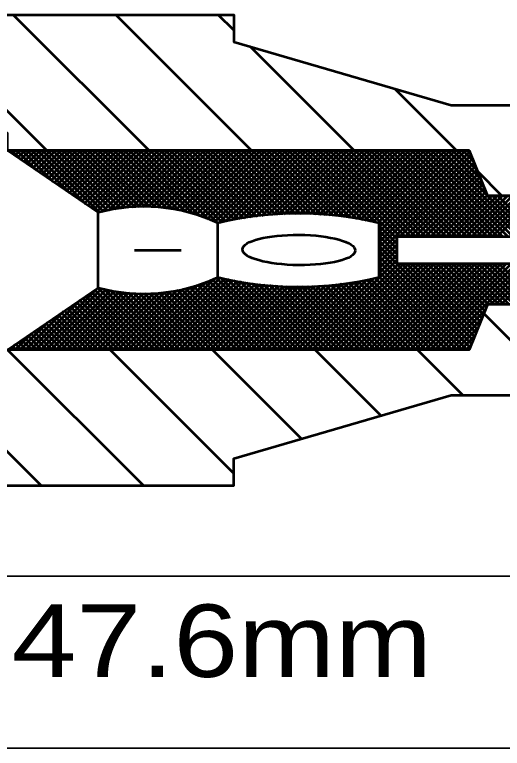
# Model space of a CAD drawing. Extents: x -32 to 824, y -6 to 538.
# Drawn here: x 645.6 to 661.75, y 243.33 to 267.63 of the extents above; entities that cross this region are included whole.
import ezdxf

# ---------------------------------------------------------------- set-up
doc = ezdxf.new("R2010")
doc.units = 0
doc.header["$LTSCALE"] = 1.1
doc.layers.add('1', color=7, linetype='Continuous', lineweight=53)

msp = doc.modelspace()

# ---------------------------------------------------------------- linework, layer by layer
at = {"layer": '1'}
for p, q in [((646.662, 263.133), (642.162, 267.633)), ((650.056, 263.133), (645.556, 267.633)), ((653.45, 263.133), (648.95, 267.633)), ((652.858, 267.12), (652.344, 267.633)), ((656.844, 263.133), (653.404, 266.574)), ((660.239, 263.133), (658.195, 265.176)), ((648.369, 261.079), (645.369, 263.133)), ((645.803, 262.836), (645.506, 263.133)), ((645.606, 262.971), (645.768, 263.133)), ((646.341, 262.468), (645.676, 263.133)), ((645.707, 262.902), (645.938, 263.133)), ((645.808, 262.833), (646.108, 263.133)), ((646.879, 262.099), (645.846, 263.133)), ((645.908, 262.764), (646.277, 263.133)), ((646.009, 262.695), (646.447, 263.133)), ((647.418, 261.731), (646.015, 263.133)), ((646.11, 262.626), (646.617, 263.133)), ((647.956, 261.362), (646.185, 263.133)), ((646.211, 262.557), (646.787, 263.133)), ((646.311, 262.488), (646.956, 263.133)), ((648.401, 261.087), (646.355, 263.133)), ((646.412, 262.419), (647.126, 263.133)), ((646.513, 262.35), (647.296, 263.133)), ((648.539, 261.119), (646.524, 263.133)), ((646.614, 262.281), (647.465, 263.133)), ((648.677, 261.15), (646.694, 263.133)), ((646.714, 262.212), (647.635, 263.133)), ((646.815, 262.143), (647.805, 263.133)), ((648.817, 261.18), (646.864, 263.133)), ((646.916, 262.074), (647.975, 263.133)), ((647.016, 262.005), (648.144, 263.133)), ((648.966, 261.201), (647.033, 263.133)), ((647.117, 261.936), (648.314, 263.133)), ((649.115, 261.221), (647.203, 263.133)), ((647.218, 261.867), (648.484, 263.133)), ((647.319, 261.798), (648.653, 263.133)), ((649.264, 261.242), (647.373, 263.133)), ((647.419, 261.73), (648.823, 263.133)), ((647.52, 261.661), (648.993, 263.133)), ((649.416, 261.26), (647.543, 263.133)), ((647.621, 261.591), (649.162, 263.133)), ((649.581, 261.265), (647.712, 263.133)), ((647.722, 261.523), (649.332, 263.133)), ((647.822, 261.454), (649.502, 263.133)), ((649.745, 261.27), (647.882, 263.133)), ((647.923, 261.385), (649.672, 263.133)), ((648.024, 261.316), (649.841, 263.133)), ((649.909, 261.275), (648.052, 263.133)), ((648.125, 261.247), (650.011, 263.133)), ((650.084, 261.271), (648.221, 263.133)), ((648.225, 261.178), (650.181, 263.133)), ((648.326, 261.109), (650.35, 263.133)), ((650.267, 261.257), (648.391, 263.133)), ((648.495, 261.108), (650.52, 263.133)), ((650.45, 261.244), (648.561, 263.133)), ((648.716, 261.159), (650.69, 263.133)), ((650.639, 261.225), (648.731, 263.133)), ((650.845, 261.188), (648.9, 263.133)), ((648.921, 261.195), (650.86, 263.133)), ((651.052, 261.151), (649.07, 263.133)), ((649.118, 261.221), (651.029, 263.133)), ((651.271, 261.101), (649.24, 263.133)), ((649.314, 261.249), (651.199, 263.133)), ((651.51, 261.032), (649.409, 263.133)), ((649.498, 261.262), (651.369, 263.133)), ((651.749, 260.963), (649.579, 263.133)), ((649.673, 261.268), (651.538, 263.133)), ((652.034, 260.848), (649.749, 263.133)), ((649.848, 261.273), (651.708, 263.133)), ((652.318, 260.734), (649.918, 263.133)), ((650.02, 261.276), (651.878, 263.133)), ((652.458, 260.763), (650.088, 263.133)), ((650.178, 261.264), (652.047, 263.133)), ((652.598, 260.793), (650.258, 263.133)), ((650.336, 261.252), (652.217, 263.133)), ((652.738, 260.823), (650.428, 263.133)), ((650.495, 261.241), (652.387, 263.133)), ((652.878, 260.853), (650.597, 263.133)), ((650.647, 261.224), (652.557, 263.133)), ((653.025, 260.875), (650.767, 263.133)), ((650.791, 261.198), (652.726, 263.133)), ((650.935, 261.172), (652.896, 263.133)), ((653.175, 260.894), (650.937, 263.133)), ((651.079, 261.146), (653.066, 263.133)), ((653.326, 260.914), (651.106, 263.133)), ((651.219, 261.117), (653.235, 263.133)), ((653.476, 260.934), (651.276, 263.133)), ((651.35, 261.079), (653.405, 263.133)), ((653.625, 260.953), (651.446, 263.133)), ((651.482, 261.04), (653.575, 263.133)), ((651.614, 261.002), (653.745, 263.133)), ((653.776, 260.973), (651.615, 263.133)), ((651.745, 260.964), (653.914, 263.133)), ((653.926, 260.993), (651.785, 263.133)), ((651.867, 260.916), (654.084, 263.133)), ((654.076, 261.012), (651.955, 263.133)), ((651.987, 260.867), (654.254, 263.133)), ((652.108, 260.818), (654.423, 263.133)), ((654.239, 261.019), (652.125, 263.133)), ((652.228, 260.769), (654.593, 263.133)), ((654.404, 261.023), (652.294, 263.133)), ((652.375, 260.746), (654.763, 263.133)), ((654.57, 261.028), (652.464, 263.133)), ((652.591, 260.792), (654.932, 263.133)), ((654.735, 261.032), (652.634, 263.133)), ((654.9, 261.036), (652.803, 263.133)), ((652.807, 260.838), (655.102, 263.133)), ((655.066, 261.04), (652.973, 263.133)), ((653.012, 260.873), (655.272, 263.133)), ((655.231, 261.045), (653.143, 263.133)), ((653.207, 260.898), (655.442, 263.133)), ((655.408, 261.038), (653.312, 263.133)), ((653.402, 260.924), (655.611, 263.133)), ((655.592, 261.023), (653.482, 263.133)), ((653.598, 260.95), (655.781, 263.133)), ((655.777, 261.008), (653.652, 263.133)), ((653.793, 260.975), (655.951, 263.133)), ((655.961, 260.994), (653.822, 263.133)), ((653.988, 261.001), (656.12, 263.133)), ((656.145, 260.979), (653.991, 263.133)), ((656.33, 260.965), (654.161, 263.133)), ((654.174, 261.017), (656.29, 263.133)), ((656.517, 260.947), (654.331, 263.133)), ((654.349, 261.022), (656.46, 263.133)), ((656.725, 260.908), (654.5, 263.133)), ((654.523, 261.026), (656.63, 263.133)), ((656.934, 260.87), (654.67, 263.133)), ((654.697, 261.031), (656.799, 263.133)), ((657.142, 260.831), (654.84, 263.133)), ((654.871, 261.035), (656.969, 263.133)), ((657.35, 260.792), (655.01, 263.133)), ((655.045, 261.04), (657.139, 263.133)), ((657.559, 260.754), (655.179, 263.133)), ((655.22, 261.044), (657.308, 263.133)), ((658.269, 260.213), (655.349, 263.133)), ((655.384, 261.039), (657.478, 263.133)), ((658.369, 260.283), (655.519, 263.133)), ((655.542, 261.027), (657.648, 263.133)), ((658.538, 260.283), (655.688, 263.133)), ((655.699, 261.014), (657.817, 263.133)), ((655.856, 261.002), (657.987, 263.133)), ((658.708, 260.283), (655.858, 263.133)), ((656.013, 260.99), (658.157, 263.133)), ((658.878, 260.283), (656.028, 263.133)), ((656.171, 260.977), (658.327, 263.133)), ((659.048, 260.283), (656.197, 263.133)), ((656.328, 260.965), (658.496, 263.133)), ((659.217, 260.283), (656.367, 263.133)), ((656.485, 260.952), (658.666, 263.133)), ((659.387, 260.283), (656.537, 263.133)), ((656.629, 260.926), (658.836, 263.133)), ((659.557, 260.283), (656.707, 263.133)), ((656.772, 260.9), (659.005, 263.133)), ((659.726, 260.283), (656.876, 263.133)), ((656.915, 260.873), (659.175, 263.133)), ((659.896, 260.283), (657.046, 263.133)), ((657.058, 260.846), (659.345, 263.133)), ((657.201, 260.82), (659.514, 263.133)), ((660.066, 260.283), (657.216, 263.133)), ((657.345, 260.793), (659.684, 263.133)), ((660.235, 260.283), (657.385, 263.133)), ((657.488, 260.767), (659.854, 263.133)), ((660.405, 260.283), (657.555, 263.133)), ((657.631, 260.74), (660.024, 263.133)), ((657.669, 260.609), (660.193, 263.133)), ((657.669, 260.439), (660.363, 263.133)), ((657.669, 260.269), (660.533, 263.133)), ((657.669, 260.1), (660.671, 263.101)), ((657.669, 259.93), (660.719, 262.98)), ((660.575, 260.283), (657.725, 263.133)), ((660.745, 260.283), (657.895, 263.133)), ((660.914, 260.283), (658.064, 263.133)), ((661.084, 260.283), (658.234, 263.133)), ((661.254, 260.283), (658.404, 263.133)), ((661.423, 260.283), (658.573, 263.133)), ((661.593, 260.283), (658.743, 263.133)), ((661.763, 260.283), (658.913, 263.133)), ((661.933, 260.283), (659.082, 263.133)), ((662.102, 260.283), (659.252, 263.133)), ((662.272, 260.283), (659.422, 263.133)), ((662.442, 260.283), (659.592, 263.133)), ((661.256, 261.639), (659.761, 263.133)), ((661.143, 261.922), (659.931, 263.133)), ((661.029, 262.204), (660.101, 263.133)), ((660.916, 262.487), (660.27, 263.133)), ((660.803, 262.77), (660.44, 263.133)), ((660.69, 263.053), (660.61, 263.133)), ((657.669, 259.76), (660.768, 262.859)), ((658.361, 260.283), (660.816, 262.738)), ((658.531, 260.283), (660.865, 262.616)), ((658.701, 260.283), (660.913, 262.495)), ((658.871, 260.283), (660.962, 262.374)), ((659.04, 260.283), (661.01, 262.253)), ((661.739, 261.633), (660.938, 262.434)), ((659.21, 260.283), (661.058, 262.132)), ((659.38, 260.283), (661.107, 262.01)), ((659.55, 260.283), (661.156, 261.889)), ((659.719, 260.283), (661.204, 261.768)), ((659.889, 260.283), (661.253, 261.647)), ((660.059, 260.283), (661.409, 261.633)), ((660.228, 260.283), (661.578, 261.633)), ((660.398, 260.283), (661.748, 261.633)), ((660.568, 260.283), (661.918, 261.633)), ((660.737, 260.283), (662.087, 261.633)), ((660.907, 260.283), (662.257, 261.633)), ((661.077, 260.283), (662.427, 261.633)), ((661.247, 260.283), (662.596, 261.633)), ((662.611, 260.283), (661.261, 261.633)), ((661.416, 260.283), (662.766, 261.633)), ((662.781, 260.283), (661.431, 261.633)), ((661.586, 260.283), (662.936, 261.633)), ((662.951, 260.283), (661.601, 261.633)), ((648.369, 258.587), (648.369, 261.079)), ((652.315, 260.733), (652.315, 258.933)), ((657.669, 258.933), (657.669, 260.733)), ((658.269, 260.043), (657.669, 260.643)), ((658.269, 259.874), (657.669, 260.474)), ((658.269, 259.704), (657.669, 260.304)), ((657.669, 259.591), (658.269, 260.191)), ((658.269, 259.534), (657.669, 260.134)), ((657.669, 259.421), (658.269, 260.021)), ((649.569, 259.833), (651.115, 259.833)), ((660.784, 256.849), (657.669, 259.964)), ((657.669, 259.251), (658.269, 259.851)), ((660.736, 256.728), (657.669, 259.795)), ((657.669, 259.082), (658.269, 259.682)), ((660.687, 256.607), (657.669, 259.625)), ((655.29, 256.533), (658.269, 259.512)), ((655.46, 256.533), (658.31, 259.383)), ((655.63, 256.533), (658.48, 259.383)), ((655.8, 256.533), (658.649, 259.383)), ((655.969, 256.533), (658.819, 259.383)), ((656.139, 256.533), (658.989, 259.383)), ((656.309, 256.533), (659.159, 259.383)), ((656.478, 256.533), (659.328, 259.383)), ((656.648, 256.533), (659.498, 259.383)), ((656.818, 256.533), (659.668, 259.383)), ((656.987, 256.533), (659.837, 259.383)), ((657.157, 256.533), (660.007, 259.383)), ((657.327, 256.533), (660.177, 259.383)), ((657.497, 256.533), (660.346, 259.383)), ((657.666, 256.533), (660.516, 259.383)), ((660.591, 256.533), (657.669, 259.455)), ((660.422, 256.533), (657.669, 259.286)), ((657.836, 256.533), (660.686, 259.383)), ((658.006, 256.533), (660.856, 259.383)), ((658.175, 256.533), (661.025, 259.383)), ((658.345, 256.533), (661.195, 259.383)), ((660.833, 256.97), (658.42, 259.383)), ((658.515, 256.533), (661.365, 259.383)), ((660.881, 257.092), (658.59, 259.383)), ((658.685, 256.533), (661.534, 259.383)), ((660.93, 257.213), (658.76, 259.383)), ((658.854, 256.533), (661.704, 259.383)), ((660.978, 257.334), (658.929, 259.383)), ((659.024, 256.533), (661.874, 259.383)), ((661.027, 257.455), (659.099, 259.383)), ((659.194, 256.533), (662.044, 259.383)), ((661.075, 257.577), (659.269, 259.383)), ((659.363, 256.533), (662.213, 259.383)), ((661.124, 257.698), (659.438, 259.383)), ((659.533, 256.533), (662.383, 259.383)), ((661.172, 257.819), (659.608, 259.383)), ((659.703, 256.533), (662.553, 259.383)), ((661.221, 257.94), (659.778, 259.383)), ((661.298, 258.033), (659.947, 259.383)), ((661.467, 258.033), (660.117, 259.383)), ((661.637, 258.033), (660.287, 259.383)), ((661.807, 258.033), (660.457, 259.383)), ((661.976, 258.033), (660.626, 259.383)), ((662.146, 258.033), (660.796, 259.383)), ((662.316, 258.033), (660.966, 259.383)), ((662.485, 258.033), (661.135, 259.383)), ((662.655, 258.033), (661.305, 259.383)), ((661.372, 258.033), (662.722, 259.383)), ((662.825, 258.033), (661.475, 259.383)), ((661.542, 258.033), (662.892, 259.383)), ((662.995, 258.033), (661.645, 259.383)), ((661.712, 258.033), (663.062, 259.383)), ((660.252, 256.533), (657.669, 259.116)), ((649.86, 256.533), (652.219, 258.892)), ((650.029, 256.533), (652.412, 258.915)), ((650.199, 256.533), (652.555, 258.889)), ((650.369, 256.533), (652.698, 258.862)), ((650.539, 256.533), (652.841, 258.836)), ((650.708, 256.533), (652.984, 258.809)), ((654.312, 256.533), (652.032, 258.813)), ((654.482, 256.533), (652.152, 258.863)), ((654.652, 256.533), (652.271, 258.914)), ((654.821, 256.533), (652.446, 258.909)), ((654.991, 256.533), (652.654, 258.87)), ((655.161, 256.533), (652.862, 258.832)), ((654.781, 256.533), (657.052, 258.804)), ((654.951, 256.533), (657.265, 258.847)), ((655.121, 256.533), (657.481, 258.893)), ((659.403, 256.533), (657.12, 258.816)), ((659.573, 256.533), (657.26, 258.846)), ((659.743, 256.533), (657.4, 258.876)), ((659.913, 256.533), (657.54, 258.906)), ((660.082, 256.533), (657.669, 258.946)), ((645.369, 256.533), (648.369, 258.587)), ((646.466, 256.533), (648.493, 258.56)), ((650.409, 256.533), (648.361, 258.581)), ((649.351, 256.533), (651.422, 258.604)), ((649.52, 256.533), (651.672, 258.685)), ((649.69, 256.533), (651.924, 258.767)), ((650.878, 256.533), (653.127, 258.782)), ((651.048, 256.533), (653.27, 258.756)), ((651.217, 256.533), (653.413, 258.729)), ((653.294, 256.533), (651.264, 258.563)), ((651.387, 256.533), (653.563, 258.709)), ((653.464, 256.533), (651.4, 258.597)), ((653.633, 256.533), (651.528, 258.639)), ((651.557, 256.533), (653.72, 258.696)), ((653.803, 256.533), (651.656, 258.68)), ((651.726, 256.533), (653.877, 258.684)), ((653.973, 256.533), (651.785, 258.721)), ((651.896, 256.533), (654.035, 258.672)), ((654.143, 256.533), (651.913, 258.763)), ((652.066, 256.533), (654.192, 258.659)), ((652.236, 256.533), (654.349, 258.647)), ((652.405, 256.533), (654.507, 258.634)), ((652.575, 256.533), (654.664, 258.622)), ((652.745, 256.533), (654.835, 258.624)), ((652.914, 256.533), (655.01, 258.628)), ((655.331, 256.533), (653.071, 258.793)), ((653.084, 256.533), (655.184, 258.633)), ((653.254, 256.533), (655.358, 258.637)), ((655.5, 256.533), (653.279, 258.754)), ((653.424, 256.533), (655.532, 258.642)), ((655.67, 256.533), (653.488, 258.716)), ((653.593, 256.533), (655.706, 258.646)), ((655.84, 256.533), (653.673, 258.7)), ((653.763, 256.533), (655.881, 258.651)), ((656.009, 256.533), (653.857, 258.686)), ((653.933, 256.533), (656.075, 258.676)), ((656.179, 256.533), (654.041, 258.671)), ((654.102, 256.533), (656.271, 258.701)), ((656.349, 256.533), (654.225, 258.656)), ((654.272, 256.533), (656.466, 258.727)), ((656.518, 256.533), (654.41, 258.642)), ((654.442, 256.533), (656.661, 258.752)), ((656.688, 256.533), (654.594, 258.627)), ((654.611, 256.533), (656.857, 258.778)), ((656.858, 256.533), (654.769, 258.622)), ((657.028, 256.533), (654.934, 258.626)), ((657.197, 256.533), (655.1, 258.631)), ((657.367, 256.533), (655.265, 258.635)), ((657.537, 256.533), (655.431, 258.639)), ((657.706, 256.533), (655.596, 258.643)), ((657.876, 256.533), (655.762, 258.648)), ((658.046, 256.533), (655.923, 258.656)), ((658.216, 256.533), (656.073, 258.675)), ((658.385, 256.533), (656.223, 258.695)), ((658.555, 256.533), (656.373, 258.715)), ((658.725, 256.533), (656.523, 258.734)), ((658.894, 256.533), (656.673, 258.754)), ((659.064, 256.533), (656.823, 258.774)), ((659.234, 256.533), (656.973, 258.793)), ((646.296, 256.533), (648.308, 258.545)), ((646.635, 256.533), (648.633, 258.53)), ((646.805, 256.533), (648.772, 258.5)), ((646.975, 256.533), (648.912, 258.47)), ((647.144, 256.533), (649.061, 258.449)), ((647.314, 256.533), (649.214, 258.433)), ((647.484, 256.533), (649.367, 258.416)), ((647.654, 256.533), (649.52, 258.4)), ((647.823, 256.533), (649.686, 258.396)), ((647.993, 256.533), (649.855, 258.395)), ((649.9, 256.533), (648.059, 258.374)), ((650.07, 256.533), (648.159, 258.443)), ((648.163, 256.533), (650.024, 258.395)), ((650.239, 256.533), (648.26, 258.512)), ((648.332, 256.533), (650.198, 258.399)), ((648.502, 256.533), (650.387, 258.418)), ((650.579, 256.533), (648.568, 258.544)), ((648.672, 256.533), (650.576, 258.437)), ((650.748, 256.533), (648.784, 258.498)), ((648.841, 256.533), (650.767, 258.458)), ((650.918, 256.533), (648.995, 258.456)), ((649.011, 256.533), (650.981, 258.503)), ((649.181, 256.533), (651.196, 258.548)), ((651.088, 256.533), (649.185, 258.436)), ((651.258, 256.533), (649.375, 258.415)), ((651.427, 256.533), (649.565, 258.396)), ((651.597, 256.533), (649.735, 258.395)), ((651.767, 256.533), (649.905, 258.395)), ((651.936, 256.533), (650.075, 258.394)), ((652.106, 256.533), (650.237, 258.403)), ((652.276, 256.533), (650.391, 258.418)), ((652.446, 256.533), (650.545, 258.434)), ((652.615, 256.533), (650.698, 258.45)), ((652.785, 256.533), (650.844, 258.474)), ((652.955, 256.533), (650.984, 258.504)), ((653.124, 256.533), (651.124, 258.533)), ((646.126, 256.533), (647.77, 258.177)), ((649.221, 256.533), (647.656, 258.099)), ((649.391, 256.533), (647.756, 258.168)), ((649.561, 256.533), (647.857, 258.236)), ((649.73, 256.533), (647.958, 258.305)), ((648.542, 256.533), (647.253, 257.823)), ((648.712, 256.533), (647.353, 257.892)), ((648.882, 256.533), (647.454, 257.961)), ((649.051, 256.533), (647.555, 258.029)), ((659.872, 256.533), (661.182, 257.842)), ((645.957, 256.533), (647.232, 257.808)), ((648.033, 256.533), (646.951, 257.616)), ((648.203, 256.533), (647.051, 257.685)), ((648.373, 256.533), (647.152, 257.754)), ((663.84, 255.033), (661.139, 257.735)), ((645.787, 256.533), (646.694, 257.44)), ((647.354, 256.533), (646.548, 257.34)), ((647.524, 256.533), (646.648, 257.409)), ((647.694, 256.533), (646.749, 257.478)), ((647.863, 256.533), (646.85, 257.547)), ((660.042, 256.533), (661.068, 257.559)), ((646.845, 256.533), (646.245, 257.133)), ((647.015, 256.533), (646.346, 257.202)), ((647.185, 256.533), (646.447, 257.271)), ((660.212, 256.533), (660.955, 257.277)), ((645.617, 256.533), (646.156, 257.072)), ((646.166, 256.533), (645.842, 256.857)), ((646.336, 256.533), (645.943, 256.926)), ((646.506, 256.533), (646.044, 256.995)), ((646.676, 256.533), (646.145, 257.064)), ((660.382, 256.533), (660.842, 256.994)), ((645.447, 256.533), (645.617, 256.703)), ((645.657, 256.533), (645.54, 256.65)), ((645.827, 256.533), (645.641, 256.719)), ((645.997, 256.533), (645.742, 256.788)), ((660.551, 256.533), (660.729, 256.711)), ((649.87, 252.033), (645.37, 256.533)), ((652.858, 252.439), (648.764, 256.533)), ((655.103, 253.588), (652.158, 256.533)), ((657.731, 254.354), (655.552, 256.533)), ((660.446, 255.033), (658.946, 256.533)), ((646.475, 252.033), (642.549, 255.959))]:
    msp.add_line(p, q, dxfattribs=at)
at = {"layer": '1', "lineweight": 35}
for p, q in [((636.106, 249.033), (669.658, 249.033)), ((673.258, 243.333), (624.058, 243.333))]:
    msp.add_line(p, q, dxfattribs=at)
at = {"layer": '1'}
for points in [[(626.506, 263.557), (626.506, 265.67), (636.106, 265.67), (636.106, 267.633), (652.858, 267.633), (652.858, 266.733), (660.058, 264.633), (669.658, 264.633), (669.658, 261.633), (661.258, 261.633), (660.658, 263.133), (645.369, 263.133), (645.369, 263.707), (640.569, 263.707), (640.569, 264.607), (639.369, 264.607), (639.369, 264.007), (638.769, 264.007), (636.669, 263.557)], [(645.369, 263.133), (660.658, 263.133), (661.258, 261.633), (669.658, 261.633), (681.658, 261.633), (681.658, 258.033), (669.658, 258.033), (661.258, 258.033), (660.658, 256.533), (645.369, 256.533)], [(626.506, 256.109), (626.506, 253.996), (636.106, 253.996), (636.106, 252.033), (652.858, 252.033), (652.858, 252.933), (660.058, 255.033), (669.658, 255.033), (669.658, 258.033), (661.258, 258.033), (660.658, 256.533), (645.369, 256.533)]]:
    msp.add_lwpolyline(points, dxfattribs=at)
msp.add_lwpolyline([(658.269, 259.383), (658.269, 260.283), (681.058, 260.283), (681.058, 259.383)], close=True, dxfattribs=at)
for centre, radius, start, end in [((649.871, 255.533), 5.746, 64.8235, 105.1491), ((654.992, 249.599), 11.451, 76.4814, 103.5186), ((649.871, 264.133), 5.746, 254.8509, 295.1765), ((654.992, 270.067), 11.451, 256.4814, 283.5186)]:
    msp.add_arc(centre, radius, start, end, dxfattribs=at)
msp.add_ellipse((655.013, 259.839), major_axis=(1.867, -0.018), ratio=0.269097, dxfattribs=at)

# ---------------------------------------------------------------- texts
at = {"layer": '1', "width": 1.2}
msp.add_text('47.6mm', height=2.4, dxfattribs=at).set_placement((645.508, 245.697))

doc.saveas('drawing.dxf')
